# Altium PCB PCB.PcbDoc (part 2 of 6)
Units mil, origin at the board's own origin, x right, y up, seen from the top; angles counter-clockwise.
Board outline 7100 x 7000 mil, 4 copper layers (Top Layer, GND, VCC, Bottom Layer), stack 61.2 mil thick; 759 components, 507 nets, 2200 pads, 452 vias.
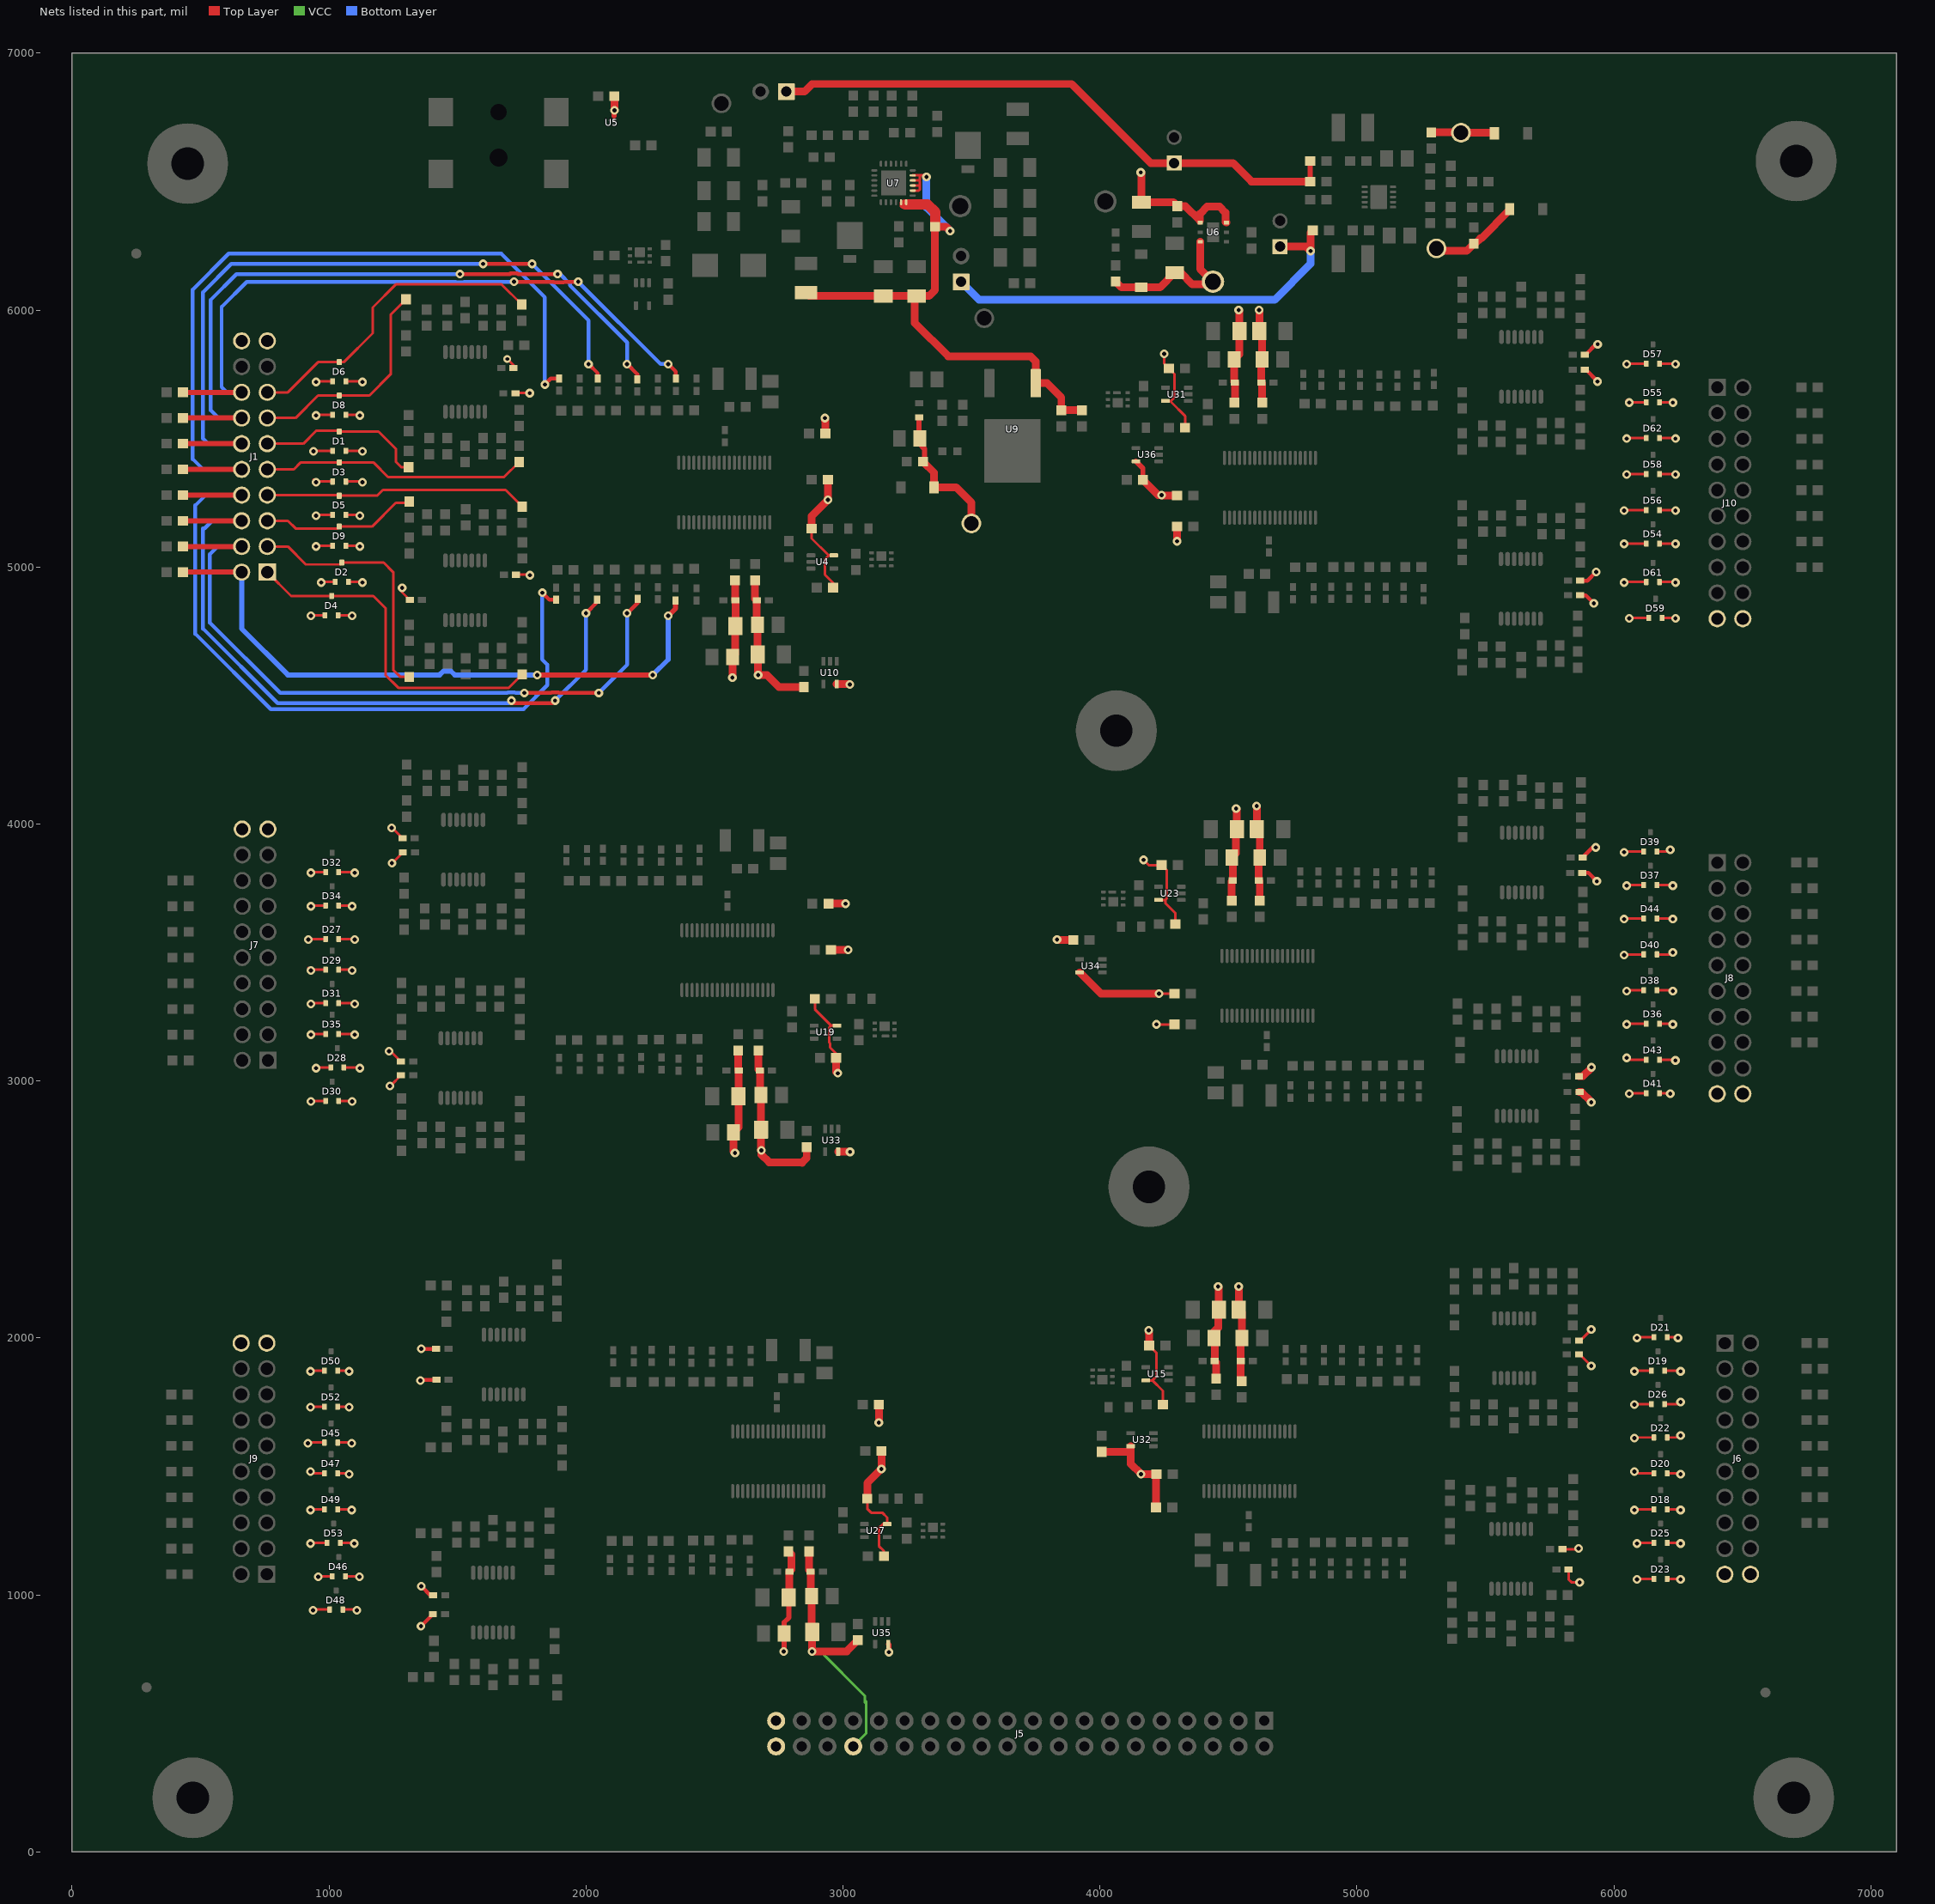
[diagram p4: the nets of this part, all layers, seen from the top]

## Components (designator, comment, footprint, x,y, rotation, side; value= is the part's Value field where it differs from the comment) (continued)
U24 "OPA4197IPWR" PW0014A_N 1679.76,1896.43 r270 top
U25 "OPA4197IPWR" PW0014A_N 1638.26,969.95 r270 top
U26 "ADS8688IDBT" DBT0038A_N 2748.26,1519.95 r270 top
U27 "SN74LVC1G17DCKR" DCK0005A_N 3128.25,1250 r0 top
U28 "OPA4197IPWR" PW0014A_N 5637.69,4914.98 r90 top
U29 "OPA4197IPWR" PW0014A_N 5639.69,5778.98 r90 top
U30 "ADS8688IDBT" DBT0038A_N 4661.89,5308.58 r90 top
U31 "SN74LVC1G17DCKR" DCK0005A_N 4300,5672.44 r180 top
U32 "SN74LVC1G17DCKR" DCK0005A_N 4164,1604 r180 top
U33 "SN74LVC1G17DCKR" DCK0005A_N 2956,2769 r270 top
U34 "SN74LVC1G17DCKR" DCK0005A_N 3966,3448 r180 top
U35 "SN74LVC1G17DCKR" DCK0005A_N 3151,853 r270 top
U36 "SN74LVC1G17DCKR" DCK0005A_N 4185,5437 r180 top
ZZ1 "This Assembly Note is for PCB labels only" AssemblyNoteLabel 11900,340 r90 top

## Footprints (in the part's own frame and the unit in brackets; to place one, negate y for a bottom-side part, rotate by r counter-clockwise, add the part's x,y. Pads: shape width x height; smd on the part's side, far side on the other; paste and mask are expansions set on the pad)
0402 [mm] "0402 from SM-752 data"
  rect 0.8x0.6 smd: 1(-0.6,0) 2(0.6,0)
  silkscreen extent -1.22,-0.52 1.22,0.52, body extent -0.55,-0.3 0.55,0.3, height 0.6
0603 [mm] "0603 from SM-752 data"
  rect 1x0.95 smd: 1(-0.8,0) 2(0.8,0)
  silkscreen extent -1.52,-0.69 1.52,0.69, body extent -0.87,-0.47 0.87,0.47, height 1
0805_HV [mil] "0805 with 30mil clearance between pads"
  rect 50x63 smd: 1(-40,0) 2(40,0)
  silkscreen extent -74,-40 74,40, body extent -43,-29 43,29, height 57
1206 [mm] "1206 from SM-752 data"
  rect 1.3x1.85 smd: 1(-1.45,0) 2(1.45,0)
  silkscreen extent -2.4,-1.21 2.4,1.21, body extent -1.7,-0.9 1.7,0.9, height 1.35
1210 [mm] "1210 from SM-752 data"
  rect 1.3x2.7 smd: 1(-1.45,0) 2(1.45,0)
  silkscreen extent -2.32,-1.57 2.32,1.57, body extent -1.7,-1.35 1.7,1.35, height 1.35
1210_280 [mm] "SMD, 2-Leads, Body 3.6x2.8mm, Height 2.8mm"
  rect 1.1x2.2 smd: 1(-1.65,0) 2(1.65,0)
  silkscreen extent -0.84,-1.4 0.84,1.4, body extent -1.8,-1.4 1.8,1.4, height 2.8
3216-18 [mm] "Based on AVX recommendation in http://www.avx.com/download/software/literature/AVX-Footprint-Library.pdf"
  rrect7% 1.4x1.8 smd: 1(-1.3,0) 2(1.3,0)
  silkscreen extent -1.9,-1.12 0.8,1.12, body extent -1.7,-0.9 1.7,0.9, height 1.82
6032-28 [mm] "Medium Density IPC based on Vishay Sprague 293D datasheet."
  rect 2.55x2.3 smd: 1(-2.375,0) 2(2.375,0)
  silkscreen extent -3.96,-1.75 3.2,1.82, body extent -3.15,-1.75 3.15,1.75, height 2.8
AssemblyNoteLabel [mil] "Assembly Note for PCB Labels"
CONN_PEC02SAAN [mm] "SULLINS"
  rrect7% 1.5x1.5 hole 1.016: 1(-1.27,0)
  round 1.5 hole 1.016: 2(1.27,0)
  silkscreen extent -2.54,-1.52 2.54,1.27, body extent -2.54,-1.27 2.54,1.27, height 8.38
CONN_ZSS-120-01-L-D-529 [mil] "Header 20x2 , 100 mil Pitch"
  rect 70x70 hole 40: 1(-950,-50)
  round 70 hole 40: 2(-950,50) 3(-850,-50) 4(-850,50) 5(-750,-50) 6(-750,50) 7(-650,-50) 8(-650,50) 9(-550,-50) 10(-550,50) 11(-450,-50) 12(-450,50) 13(-350,-50) 14(-350,50) 15(-250,-50) 16(-250,50) 17(-150,-50) 18(-150,50) 19(-50,-50) 20(-50,50) 21(50,-50) 22(50,50) 23(150,-50) 24(150,50) 25(250,-50) 26(250,50) 27(350,-50) 28(350,50) 29(450,-50) 30(450,50) 31(550,-50) 32(550,50) 33(650,-50) 34(650,50) 35(750,-50) 36(750,50) 37(850,-50) 38(850,50) 39(950,-50) 40(950,50)
  silkscreen extent -1075,-190 1075,183, body extent -1075,-190 1075,183, height 528
CUI_PJ-002AH-SMT [mm] "CUI"
  rect 2.8x2.4 smd: 1(-3.05,5.7) 1A(3.05,5.7) 2(-3.05,-5.7) 3(3.05,-5.7)
  round 1 hole 1.6 unplated: MH1(-3.05,0)
  round 1.524 hole 1.8 unplated: MH2(1.45,0)
  silkscreen extent -8.05,-4.5 6.75,5.45, body extent -8.05,-6.3 6.75,6.3, height 11.2
DBT0038A_N [mm] "TSSOP, 38-Leads, Body 9.7x4.4mm, Pitch 0.5mm, IPC Medium Density"
  oval 1.4x0.3 smd: 1(-2.95,4.5) 2(-2.95,4) 3(-2.95,3.5) 4(-2.95,3) 5(-2.95,2.5) 6(-2.95,2) 7(-2.95,1.5) 8(-2.95,1) 9(-2.95,0.5) 10(-2.95,0) 11(-2.95,-0.5) 12(-2.95,-1) 13(-2.95,-1.5) 14(-2.95,-2) 15(-2.95,-2.5) 16(-2.95,-3) 17(-2.95,-3.5) 18(-2.95,-4) 19(-2.95,-4.5) 20(2.95,-4.5) 21(2.95,-4) 22(2.95,-3.5) 23(2.95,-3) 24(2.95,-2.5) 25(2.95,-2) 26(2.95,-1.5) 27(2.95,-1) 28(2.95,-0.5) 29(2.95,0) 30(2.95,0.5) 31(2.95,1) 32(2.95,1.5) 33(2.95,2) 34(2.95,2.5) 35(2.95,3) 36(2.95,3.5) 37(2.95,4) 38(2.95,4.5)
  silkscreen extent -3.5,-4.9 1.5,4.9, body extent -3.21,-4.85 3.21,4.85, height 1.2
DCK0005A_N [mm] "SOT353, 5-Leads, Body 2x1.3mm, Pitch 0.65mm, Lead Span 2.1mm, IPC Medium Density"
  rrect25% 0.85x0.4 smd: 1(-1.125,0.65) 2(-1.125,0) 3(-1.125,-0.65) 4(1.125,-0.65) 5(1.125,0.65)
  silkscreen extent -1.48,-1.02 0.55,1.1, body extent -1.14,-1 1.14,1, height 0.95
DQK0006C [mm] "WSON"
  rrect12% 0.9x0.86 on Top Paste: 0(0,0.325)
  rrect34% 0.7x0.29 on Top Paste: 0(0.095,-0.65)
  rrect33% 0.45x0.3 smd: 1(-0.975,0.65) 2(-0.975,0) 3(-0.975,-0.65) 4(0.975,-0.65) 5(0.975,0) 6(0.975,0.65)
  rrect33% 0.75x0.3 smd paste-0.15: 7(0.095,-0.65)
  rrect11% 1x0.95 smd paste-0.5: 8(0,0.325)
  silkscreen extent -1.15,-1.15 1.15,1.15, body extent -1,-1 1,1, height 0.82
DSC0010J [mm] "SON, 10-Leads, Body 3x3mm, Pitch 0.5mm, Thermal Pad 2.4x1.65mm, TI Recommended"
  rrect40% 0.6x0.25 smd: 1(-1.4,1) 2(-1.4,0.5) 3(-1.4,0) 4(-1.4,-0.5) 5(-1.4,-1) 6(1.4,-1) 7(1.4,-0.5) 8(1.4,0) 9(1.4,0.5) 10(1.4,1)
  rrect40% 0.25x0.34 on Top Paste: 11(-0.25,-1.53) 11(-0.25,1.53) 11(0.25,-1.53) 11(0.25,1.53)
  rrect9% 1.5x1.06 on Top Paste: 11(0,-0.63) 11(0,0.63)
  rrect12% 1.65x2.4 smd paste-1 mask-2: 11(0,0)
  Top Layer region: -0.775,-1.25 -0.425,-1.25 -0.425,-1.65 -0.417,-1.688 -0.396,-1.721 -0.363,-1.742 -0.325,-1.75 -0.325,-1.75 -0.325,-1.75 -0.175,-1.75 -0.175,-1.75 -0.137,-1.742 -0.104,-1.721 -0.083,-1.688 -0.075,-1.65 -0.075,-1.65 -0.075,-1.25 0.075,-1.25 0.075,-1.65 0.083,-1.688 0.104,-1.721 0.137,-1.742 0.175,-1.75 0.175,-1.75 0.175,-1.75 0.325,-1.75 0.325,-1.75 0.363,-1.742 0.396,-1.721 0.417,-1.688 0.425,-1.65 0.425,-1.65 0.425,-1.25 0.775,-1.25 0.813,-1.242 0.846,-1.221 0.867,-1.188 0.875,-1.15 0.875,-1.15 0.875,1.15 0.867,1.188 0.846,1.221 0.813,1.242 0.775,1.25 0.775,1.25 0.425,1.25 0.425,1.65 0.417,1.688 0.396,1.721 0.363,1.742 0.325,1.75 0.325,1.75 0.175,1.75 0.137,1.742 0.104,1.721 0.083,1.688 0.075,1.65 0.075,1.65 0.075,1.25 -0.075,1.25 -0.075,1.65 -0.083,1.688 -0.104,1.721 -0.137,1.742 -0.175,1.75 -0.175,1.75 -0.325,1.75 -0.363,1.742 -0.396,1.721 -0.417,1.688 -0.425,1.65 -0.425,1.65 -0.425,1.25 -0.775,1.25 -0.813,1.242 -0.846,1.221 -0.867,1.188 -0.875,1.15 -0.875,1.15 -0.875,-1.15 -0.867,-1.188 -0.846,-1.221 -0.813,-1.242 -0.775,-1.25
  silkscreen extent -1.63,-1.63 1.63,1.63, body extent -1.5,-1.5 1.5,1.5, height 0.81
FCC_disclaimer [mil]
Fiducial10-20 [mm]
  round 1 smd mask+0.5: 1(0,0)
  Top Layer keep-out circle w1.178: c0,0 r0.5
Keystone5010 [mil] "Keystone Multipurpose loops"
  round 87 hole 63: 1(0,0)
  silkscreen extent -70,-70 70,70, body extent -63,-63 63,62, height 319
Keystone5126 [mil] "Keystone Multipurpose loops"
  round 87 hole 63: 1(0,0)
  silkscreen extent -70,-70 70,70, body extent -63,-63 63,62, height 319
Keystone_1902C#1 [mil] "Hex Standoff, 4-40 threaded, nylon"
  body extent -145,-126 146,126, height 501
Keystone_1902C#2 [mil] "Hex Standoff, 4-40 threaded, nylon"
  round 1 on Mech4: 0(0,0)
  body extent -145,-126 146,126, height 501
KVU0003A_N [mm] "DPAK, 3-Leads, Body 6.6x6.1mm, Pitch 2.29mm, IPC Medium Density"
  rrect10% 2.8x1 smd: 1(-4.2,2.29) 3(-4.2,-2.29)
  rrect10% 0.98x1.13 on Top Paste: 4(0.14,1.995) 4(0.14,0.665) 4(0.14,-0.665) 4(0.14,-1.995) 4(1.32,1.995) 4(1.32,0.665) 4(1.32,-0.665) 4(1.32,-1.995) 5(2.5,1.995) 5(2.5,-0.665) 5(2.5,0.665) 5(2.5,-1.995) 6(3.68,1.995) 6(3.68,-0.665) 6(3.68,0.665) 6(3.68,-1.995) 7(4.86,1.995) 7(4.86,-0.665) 7(4.86,0.665) 7(4.86,-1.995)
  rrect2% 6.3x5.55 smd paste-3: 4(2.5,0)
  silkscreen extent -4.35,-3.35 -1.05,3.47, body extent -5.05,-3.26 5.05,3.26, height 2.41
Label_650x200 [mil] "Thermal Transfer Label"
  silkscreen extent -325,-100 325,100, body extent -325,-100 325,100, height 1
LDE06A [mm] "PSON, 6-Leads, Body 2.92x3.29 mm, Pitch 0.95mm, NSC Recommended"
  rect 0.5x0.35 smd paste-0.175 mask+0.051: 1(-1.295,0.95) 2(-1.295,0) 3(-1.295,-0.95) 4(1.295,-0.95) 5(1.295,0) 6(1.295,0.95)
  rect 1.2x1.92 smd paste-0.6 mask+0.051: 7(0,0)
  silkscreen extent -2.52,-1.66 1.85,1.67, body extent -1.69,-1.51 1.69,1.51, height 0.8
"LG L29K_GREEN" [mm] "OSRAM"
  rect 0.8x0.8 smd paste-0.4: 1(-0.75,0) 2(0.75,0)
  silkscreen extent -0.1,-0.5 1.45,0.5, body extent -0.9,-0.45 0.9,0.45, height 0.67
LG_M67K_Green [mm] "SMD, 2-Leads, Body 2x1.4mm, Pitch 2mm"
  rect 0.8x1 smd mask+0: 1(-1,0) 2(1,0)
  silkscreen extent -2.1,-1 1.05,1, body extent -1.05,-0.75 1.05,0.75, height 1.4
Mill-Max_0253-0-15-15-30-27-10-0 [mm] "Pin Receptacle, Dia 0.015-0.025\", Length 0.173\", TH"
  round 1.95 hole 1.448: 1(0,0)
  silkscreen extent -1.4,-1.4 1.4,1.4, body extent -0.91,-0.91 0.91,0.91, height 0.79
MMZ1608_095 [mm] "TDK"
  rect 0.6x0.8 smd: 1(-0.7,0) 2(0.7,0)
  silkscreen extent -0.15,-0.58 0.15,0.58, body extent -0.87,-0.47 0.87,0.47, height 0.95
"NY PMS 440 0025 PH" [mm] "4-40 nylon screw and mounting hole"
  round 8 hole 3.2: 1(0,0)
  body extent -3.3,-3.3 3.3,3.3, height 2.69
Pb-Free_Overlay_Small [mil]
  silkscreen extent -46,-46 46,46
POWERMITE [mil] "On Semi recommended land pattern, 457-04.pdf Rev 04E dated 2008-11-26"
  rect 105x100 smd: 1(-46,0)
  rect 30x50 smd: 2(46,0)
  silkscreen extent -124,-63 61,63, body extent -94,-40 59,40, height 45
PW0014A_N [mm] "TSOP, 14-Leads, Body 5x4.4mm, Pitch 0.65mm, IPC Medium Density"
  oval 1.4x0.45 smd: 1(-2.95,1.95) 2(-2.95,1.3) 3(-2.95,0.65) 4(-2.95,0) 5(-2.95,-0.65) 6(-2.95,-1.3) 7(-2.95,-1.95) 8(2.95,-1.95) 9(2.95,-1.3) 10(2.95,-0.65) 11(2.95,0) 12(2.95,0.65) 13(2.95,1.3) 14(2.95,1.95)
  silkscreen extent -3.4,-2.55 1.85,2.55, body extent -3.21,-2.5 3.21,2.5, height 1
RGE0024B [mm] "QFN, 24-Leads, Body 4x4mm, Pitch 0.5mm, Thermal Pad 2.45x2.45mm, TI Recommended"
  oval 0.6x0.24 smd: 1(-1.9,1.25) 2(-1.9,0.75) 3(-1.9,0.25) 4(-1.9,-0.25) 5(-1.9,-0.75) 6(-1.9,-1.25) 13(1.9,-1.25) 14(1.9,-0.75) 15(1.9,-0.25) 16(1.9,0.25) 17(1.9,0.75) 18(1.9,1.25)
  oval 0.24x0.6 smd: 7(-1.25,-1.9) 8(-0.75,-1.9) 9(-0.25,-1.9) 10(0.25,-1.9) 11(0.75,-1.9) 12(1.25,-1.9) 19(1.25,1.9) 20(0.75,1.9) 21(0.25,1.9) 22(-0.25,1.9) 23(-0.75,1.9) 24(-1.25,1.9)
  rect 2.45x2.45 smd paste-1.225: 25(0,0)
  silkscreen extent -2.22,-2.22 2.22,2.22, body extent -2.07,-2.07 2.07,2.07, height 1.01
SOD-123 [mm] "On Semi recommended land pattern"
  rect 0.915x1.22 smd: 1(-1.637,0) 2(1.637,0)
  silkscreen extent -2.74,-1.17 2.03,1.17, body extent -1.93,-0.9 1.93,0.9, height 1.35
SOT-323 [mm] "Diodes Inc recommended land pattern.  2016-02-24"
  rrect21% 0.6x0.47 smd: 1(-0.95,0.65) 2(-0.95,-0.65) 3(0.95,0)
  silkscreen extent -1.14,-1.22 0.77,1.22, body extent -1.13,-1.13 1.12,1.12, height 1.13
Sullins_SBH11-xxxC-D10-ST [mm] "Header (Shrouded), 2.54mm, 10x2, TH"
  rect 1.7x1.7 hole 1.2: 1(-1.27,11.43)
  round 1.7 hole 1.2: 2(1.27,11.43) 3(-1.27,8.89) 4(1.27,8.89) 5(-1.27,6.35) 6(1.27,6.35) 7(-1.27,3.81) 8(1.27,3.81) 9(-1.27,1.27) 10(1.27,1.27) 11(-1.27,-1.27) 12(1.27,-1.27) 13(-1.27,-3.81) 14(1.27,-3.81) 15(-1.27,-6.35) 16(1.27,-6.35) 17(-1.27,-8.89) 18(1.27,-8.89) 19(-1.27,-11.43) 20(1.27,-11.43)
  silkscreen extent -5.25,-16.45 4.4,16.45, body extent -4.4,-16.45 4.7,16.45, height 9.11
TI_Stacked_Overlay_Small [mil]
  silkscreen extent -418,-98 418,98
TSW-102-07-G-S [mm] "Samtec 100mil, 1x2, 230 mil above insulator"
  rrect6% 1.65x1.65 hole 1.016: 1(-1.27,0)
  round 1.65 hole 1.016: 2(1.27,0)
  silkscreen extent -2.54,-1.27 2.54,1.65, body extent -2.54,-1.27 2.54,1.27, height 8.38
VLF504012MT [mm] "TDK"
  rect 1.3x2.2 smd: 1(-1.45,0) 2(1.45,0)
  silkscreen extent -2.2,-2.7 2.2,2.7, body extent -2.15,-2.65 2.15,2.65, height 1.2
YFP0004ABAB [mm] "TI DSBGA 0.806x0.806mm"
  round 0.23 smd paste-0.13 mask+0.038: A1(-0.2,0.2) A2(0.2,0.2) B1(-0.2,-0.2) B2(0.2,-0.2)
  silkscreen extent -0.5,-0.5 0.5,0.5, body extent -0.43,-0.43 0.43,0.43, height 0.5

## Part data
C1 C2 C11 C12 C76 C77 C86 C87 C114 C115 C124 C125 C152 C153 C162 C163 C190 C191 C200 C201 C228 C229 C238 C239: "CAP, CERM, 0.1 µF, 50 V,+/- 10%, X7R, 0603"
C3 C4 C17 C18 C30 C31 C35 C36 C78 C79 C92 C93 C105 C106 C110 C111 C116 C117 C130 C131 C143 C144 C148 C149 C154 C155 C168 C169 C181 C182 C186 C187 C192 C193 C206 C207 C219 C220 C224 C225 C230 C231 C244 C245 C257 C258 C262 C263: "CAP, CERM, 47 pF, 50 V,+/- 5%, C0G/NP0, 0603"
C5 C8 C80 C83 C118 C121 C156 C159 C194 C197 C232 C235: "CAP, CERM, 1 µF, 10 V, +/- 10%, X7R, 0805"
C6 C9 C81 C84 C119 C122 C157 C160 C195 C198 C233 C236: "CAP, TA, 10 µF, 10 V, +/- 20%, 3 ohm, SMD"
C7 C10 C82 C85 C120 C123 C158 C161 C196 C199 C234 C237: "CAP, CERM, 0.1 µF, 10 V, +/- 10%, X5R, 0402"
C13 C14 C22 C23 C32 C33 C37 C38 C88 C89 C97 C98 C107 C108 C112 C113 C126 C127 C135 C136 C145 C146 C150 C151 C164 C165 C173 C174 C183 C184 C188 C189 C202 C203 C211 C212 C221 C222 C226 C227 C240 C241 C248 C250 C259 C260 C264 C265: "CAP, CERM, 100 pF, 50 V,+/- 1%, C0G/NP0, 0603"
C15 C16 C19 C20 C21 C27 C28 C29 C48 C90 C91 C94 C95 C96 C102 C103 C104 C128 C129 C132 C133 C134 C140 C141 C142 C166 C167 C170 C171 C172 C178 C179 C180 C204 C205 C208 C209 C210 C216 C217 C218 C242 C243 C246 C247 C249 C254 C255 C256: "CAP, CERM, 0.01 µF, 50 V,+/- 10%, X7R, 0603"
C24 C99 C137 C175 C213 C251: "CAP, CERM, 10 µF, 10 V,+/- 10%, X7R, 0805"
C25 C100 C138 C176 C214 C252: "CAP, CERM, 22 µF, 16 V,+/- 10%, X7R, 1210"
C26 C101 C139 C177 C215 C253 C272: "CAP, CERM, 1 µF, 16 V,+/- 10%, X7R, 0603"
C34 C75 C109 C147 C185 C223 C261 C266 C267 C268 C269 C270 C271 C273: "CAP, CERM, 0.1 µF, 16 V, +/- 10%, X7R, 0603"
C39: library part GRM31CR71E106KA12L, "CAP, CERM, 10uF, 25V, +/-10%, X7R, 1206"
C40: "CAP, CERM, 0.1uF, 25V, +/-5%, X7R, 0603"
C41 C43 C44 C45 C47 C54 C56 C57 C58 C59: library part C3216X7R1E475M, "CAP, CERM, 4.7 µF, 25 V, +/- 20%, X7R, 1206"
C42: "CAP, TA, 4.7 µF, 25 V, +/- 10%, 2 ohm, SMD"
C46 C51 C60 C67: "CAP, CERM, 0.01 µF, 6.3 V, +/- 10%, X7R, 0603"
C49: library part C0603C224K4RACTU, "CAP, CERM, 0.22 µF, 6.3 V, +/- 10%, X7R, 0603"
C50 C52: "CAP, CERM, 10 pF, 50 V, +/- 5%, C0G/NP0, 0603"
C53 C61 C65: "CAP, CERM, 0.1 µF, 25 V,+/- 5%, X7R, 0603"
C55 C63 C69: "CAP, CERM, 1 µF, 25 V, +/- 10%, X5R, 0603"
C62 C68: library part GMK325AB7106MM-T, "CAP, CERM, 10uF, 35V, +/-20%, X7R, 1210"
C64 C66: "CAP, CERM, 2.2uF, 10V, +/-10%, X7R, 0805"
C70: library part C2012X5R1H475K125AB, "CAP, CERM, 4.7uF, 50V, +/-10%, X5R, 0805"
C71 C74: "CAP, CERM, 0.1uF, 50V, +/-10%, X7R, 0603"
C72 C73: library part GRM188R61H105KAALD, "CAP, CERM, 1uF, 50V, +/-10%, X5R, 0603"
D1 D2 D3 D4 D5 D6 D8 D9 D18 D19 D20 D21 D22 D23 D25 D26 D27 D28 D29 D30 D31 D32 D34 D35 D36 D37 D38 D39 D40 D41 D43 D44 D45 D46 D47 D48 D49 D50 D52 D53 D54 D55 D56 D57 D58 D59 D61 D62: "Diode, TVS, Uni, 70 V, SOT-323"
D7 D13 D17 D24 D33 D42 D51 D60: "LED, Green, SMD"
D10 D15: "Diode, Schottky, 20 V, 1 A, POWERMITE"
D11 D14: "Diode, Zener, 15V, 1W, SOD-123"
D12: "Diode, Zener, 5.6 V, 500 mW, SOD-123"
D16: library part MMSZ4685-V, "Diode, Zener, 3.6V, 500mW, SOD-123"
FB1: "Ferrite Bead, 1000 ohm @ 100 MHz, 0.3 A, 0603"
FID1 FID2 FID3: "Fiducial mark.  There is nothing to buy or mount."
H1 H2 H3 H4 H9 H10: "Machine Screw, Round, #4-40 x 1/4, Nylon, Philips panhead"
H5 H6 H7 H8 H11 H12: "Standoff, Hex, 0.5\"L #4-40 Nylon"
J1 J6 J7 J8 J9 J10: "Header (Shrouded), 2.54mm, 10x2, Gold, Black, TH"
J2 J4: library part TSW-102-07-G-S, "Header, 100mil, 2x1, Gold, TH"
J3: "Power Jack, SMT"
J5: "Elevated Header, 100 mil, 20x2, TH"
J11 J12: "Header, 100mil, 2x1, Tin, TH"
L1 L2: "Inductor, Shielded, Ferrite, 4.7 µH, 1.83 A, 0.1 ohm, SMD"
LBL1: library part THT-14-423-10, "Thermal Transfer Printable Labels, 0.650\" W x 0.200\" H - 10,000 per roll"
Logo1: library part TI_Logo, "Texas Instrument Corporate Signature"
Logo2: library part Pb-Free
Logo3: library part FCC_disclaimer, "FCC_disclaimer"
Q1 Q2 Q3 Q4 Q5 Q6 Q7: "MOSFET, N-CH, 30 V, 22 A, DQK0006C (WSON-6)"
R1 R2 R3 R4 R18 R19 R20 R21 R35 R36 R37 R38 R40 R41 R44 R45 R73 R74 R75 R76 R90 R91 R92 R93 R107 R108 R109 R110 R112 R113 R116 R117 R118 R119 R120 R121 R135 R136 R137 R138 R152 R153 R154 R155 R157 R158 R161 R162 R163 R164 R165 R166 R180 R181 R182 R183 R197 R198 R199 R200 R202 R203 R206 R207 R208 R209 R210 R211 R225 R226 R227 R228 R242 R243 R244 R245 R247 R248 R251 R252 R253 R254 R255 R256 R270 R271 R272 R273 R287 R288 R289 R290 R292 R293 R296 R297: "RES, 51 k, 5%, 0.1 W, 0603"
R5 R6 R7 R8 R9 R10 R11 R12 R47 R51 R53 R58 R59 R61 R65 R67 R77 R78 R79 R80 R81 R82 R83 R84 R122 R123 R124 R125 R126 R127 R128 R129 R167 R168 R169 R170 R171 R172 R173 R174 R212 R213 R214 R215 R216 R217 R218 R219 R257 R258 R259 R260 R261 R262 R263 R264 R298 R299 R300 R301 R302 R303 R304 R305 R306 R307 R308 R309: "RES, 0, 5%, 0.1 W, 0603"
R13 R14 R15 R17 R22 R24 R25 R26 R27 R28 R29 R30 R31 R32 R33 R34 R85 R86 R87 R89 R94 R96 R97 R98 R99 R100 R101 R102 R103 R104 R105 R106 R130 R131 R132 R134 R139 R141 R142 R143 R144 R145 R146 R147 R148 R149 R150 R151 R175 R176 R177 R179 R184 R186 R187 R188 R189 R190 R191 R192 R193 R194 R195 R196 R220 R221 R222 R224 R229 R231 R232 R233 R234 R235 R236 R237 R238 R239 R240 R241 R265 R266 R267 R269 R274 R276 R277 R278 R279 R280 R281 R282 R283 R284 R285 R286: "RES, 357, 1%, 0.063 W, 0402"
R16 R23 R88 R95 R133 R140 R178 R185 R223 R230 R268 R275: "RES, 47.0 k, 1%, 0.1 W, 0603"
R39 R43 R68 R72 R111 R115 R156 R160 R201 R205 R246 R250 R291 R295: "RES, 300, 5%, 0.1 W, 0603"
R42 R71 R114 R159 R204 R249 R294: "RES, 0, 1%, 0.1 W, AEC-Q200 Grade 0, 0603"
R46: "RES, 0 ohm, 5%, 0.25W, 1206"
R48: "RES, 820, 1%, 0.1 W, 0603"
R49: "RES, 576 k, 1%, 0.1 W, 0603"
R50 R54 R55: "RES, 49.9 k, 0.1%, 0.1 W, 0603"
R52: library part RC0603FR-07620KL, "RES SMD 620K OHM 1% 1/10W 0603"
R56: library part RT0603DRE071RL, "RES SMD 1 OHM 5% 1/10W 0603"
R57: "RES, 1.0 k, 5%, 0.1 W, 0603"
R60 R62: "RES, 274 k, 1%, 0.1 W, 0603"
R63: "RES, 31.6 k, 1%, 0.1 W, 0603"
R64: "RES, 300 ohm, 5%, 0.1W, 0603"
R66: "RES, 27.4 k, 1%, 0.1 W, 0603"
R69 R310 R311 R312 R313 R314 R315 R316 R317 R318 R319 R320 R321 R322 R323 R324 R325 R326 R327 R328 R329 R330 R331 R332 R333 R334 R335 R336 R337 R338: "RES, 0, 5%, 0.063 W, 0402"
R70: library part CRCW0805330KJNEA, "RES, 0 ohm, 5%, 0.125W, 0805"
TP1 TP5: library part 5010, "Test Point, Multipurpose, Red, TH"
TP2 TP4 TP6 TP7 TP8: library part 0253-0-15-15-30-27-10-0, "Pin Receptacle, Dia 0.015-0.025\", Length 0.173\", Gold, TH"
TP3: library part 5126, "Test Point, Multipurpose, Green, TH"
U1 U2 U12 U13 U16 U17 U20 U21 U24 U25 U28 U29: "36-V, Precision, Rail-to-Rail Input Output, Low Offset Voltage Op Amp, PW0014A (TSSOP-14)"
U3 U14 U18 U22 U26 U30: "16-Bit, 500-kSPS, 8-Channel, Single-Supply, SAR ADCs with Bipolar Input Ranges, DBT0038A (TSSOP-38)"
U4 U10 U11 U15 U19 U23 U27 U31 U32 U33 U34 U35 U36: "SINGLE SCHMITT-TRIGGER BUFFER, DCK0005A (SOT-SC70-5)"
U5: "Single Channel Ultra-Low Resistnace Load Switch, YFP0004ABAB (DSBGA-4)"
U6: "Micropower 250 mA Low-Noise Ultra Low-Dropout Regulator, 6-pin LLP, Pb-Free"
U7: "Postive and Negative Output DC-DC Converter, 2.7 to 5.5 V, -40 to 85 degC, 24-pin QFN (RGE24), Green (RoHS & no Sb/Br)"
U8: "Wide-VIN (±33 V), 150-mA, Spilt-Rail Output, Positive and Negative LDO Voltage Regulator with Startup Tracking, DSC0010J"
U9: "Automotive 300-mA 40-V Low-Dropout Regulator With Ultra-Low Quiescent Current, KVU0003A (TO-252-3)"
ZZ1: library part AssemblyNoteLabel

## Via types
v1: diameter 34, hole 16, Top Layer to Bottom Layer, 440 vias
v2: diameter 19.68, hole 7.87, Top Layer to Bottom Layer, 11 vias
v3: diameter 30, hole 14, Top Layer to Bottom Layer, 1 vias

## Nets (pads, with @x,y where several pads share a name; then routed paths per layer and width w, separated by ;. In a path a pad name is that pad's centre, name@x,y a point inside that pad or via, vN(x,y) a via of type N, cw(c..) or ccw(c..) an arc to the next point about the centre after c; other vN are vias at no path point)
+3.3V: C8.1 C9.1 C10.1 C34.1 C70.1 C71.1 C83.1 C84.1 C85.1 C109.1 C121.1 C122.1 C123.1 C147.1 C159.1 C160.1 C161.1 C185.1 C197.1 C198.1 C199.1 C223.1 C235.1 C236.1 C237.1 C261.1 C266.1 C267.1 C268.1 C269.1 C270.1 C271.1 D16.1 FB1.2 J5.34 R16.2 R23.2 R39.2 R88.2 R95.2 R111.2 R133.2 R140.2 R156.2 R178.2 R185.2 R201.2 R223.2 R230.2 R246.2 R268.2 R275.2 R291.2 R299.2 R301.2 R303.2 R305.2 R307.2 R309.2 TP6.1 U4.5 U10.5 U15.5 U19.5 U23.5 U27.5 U31.5 U32.5 U33.5 U34.5 U35.5 U36.5 | length 8080.9
  Top Layer w10: v1@2681.18,2731.18 v1(2682.36,2730) ; R39.2@2878.5,5150 2878.5,5111.5 2944.41,5045.59 2945.59,5045.59 ; v1(2880,780) v1@2880.15,780.15 ; R156.2@2890.87,3320 2890.87,3279.13 2954.41,3215.59 ; C34.1@2961.5,4920 2961.5,4938.5 2930,4970 2930,5030 2945.59,5045.59 ; U4.5@2964.29,5045.59 2945.59,5045.59 ; C147.1@2973.86,3090 2973.86,3106.14 2950,3130 2950,3146.45 2947.05,3149.4 2947.05,3208.23 2954.41,3215.59 ; U19.5@2976.65,3215.59 2954.41,3215.59 ; R246.2@3094.86,1374.17 3094.86,1335.14 3110,1320 3153.15,1320 3172.54,1300.61 U27.5@3172.54,1275.59 3155.59,1275.59 3140,1260 3140,1190 3159.75,1170.25 C223.1@3159.75,1150 ; R223.2@3139.75,1739.95 R223.2@3140,1739.7 ; v1(4170,3860) 4190,3840 C185.1@4240.55,3840 4260,3820.55 4260,3710 4254.41,3704.41 ; U15.5@4179.06,1834.41 4204.41,1834.41 ; C109.1@4191.85,1970 4220,1941.85 4220,1850 4204.41,1834.41 ; v1(4220,3220) R185.2@4290.55,3220 ; U23.5@4227.75,3704.41 4254.41,3704.41 ; v1(4230,3340) R178.2@4290.55,3340 ; R111.2@4244.84,1740 4244.84,1793.98 4204.41,1834.41 ; v1(4250,5830) 4250,5790.94 C261.1@4268.5,5772.44 4290,5750.94 4290,5660 4276.85,5646.85 4276.85,5642.44 4331.5,5587.8 R291.2@4331.5,5542.44 ; R201.2@4293.54,3610 4293.54,3653.15 4254.41,3692.28 4254.41,3704.41
  Top Layer w20: C199.1@2868.26,1096.33 C199.1@2874.63,1089.95 ; C197.1@2874.63,999.01 C197.1@2878.26,995.38 ; C198.1@2878.26,857.27 C198.1@2880.15,855.38 ; U35.5@3176.59,808.71 3179,806.3 v1(3179,777) ; FB1.2@3296.18,5582.83 3296.18,5503.82 C70.1@3300,5500 3300,5477 3317,5460 3317,5415.5 C71.1@3311.5,5410 ; U36.5@4140.71,5411.41 4167.5,5384.62 C271.1@4167.5,5339
  Top Layer w30: R299.2@2658.26,4948.5 2658.26,4876.38 C10.1@2664.63,4870 2664.63,4779.01 C8.1@2668.26,4775.38 2668.26,4660.56 C9.1@2668.82,4660 2668.82,4591.18 2670,4590 v1(2670,4580) 2704,4580 2751.5,4532.5 C266.1@2848,4532.5 ; R303.2@2670.62,3118.5 2670.62,3046.38 C123.1@2677,3040 2677,2949.01 C121.1@2680.62,2945.38 2680.62,2810.56 C122.1@2681.18,2810 v1@2681.18,2731.18 ; v1(2682.36,2730) 2682.36,2713.64 2713,2683 2840,2683 2841,2682 2859,2700 C268.1@2859,2742.5 ; C199.1@2868.26,1096.33 R307.2@2868.26,1168.45 ; C197.1@2874.63,999.01 C199.1@2874.63,1089.95 ; C198.1@2878.26,857.27 C197.1@2878.26,995.38 ; R39.2@2878.5,5150 2878.5,5198.5 v1(2941.5,5261.5) R23.2@2941.5,5339.95 ; v1(2880,780) 3014.5,780 C270.1@3058,823.5 ; v1@2880.15,780.15 C198.1@2880.15,855.38 ; v1(2930,5580) 2930,5570 2931.5,5568.5 R16.2@2931.5,5519.95 ; R133.2@2943.86,3689.95 2999.95,3689.95 3000,3690 v1(3010,3690) ; R140.2@2953.86,3509.95 v1(3020,3510) v1(3020,3510) ; C147.1@2973.86,3090 2973.86,3036.14 v1(2980,3030) ; U10.5@2975.59,4544.71 3025.29,4544.71 v1(3027,4543) ; U33.5@2981.59,2724.71 3027.29,2724.71 v1(3028,2724) ; R246.2@3094.86,1374.17 3094.86,1434.86 v1(3150,1490) 3150,1559.7 R230.2@3149.75,1559.95 ; v1(3140,1670) R223.2@3140,1739.7 ; C71.1@3311.5,5410 3354.47,5367.03 D16.1@3354.47,5310 3440,5310 3500,5250 TP6.1@3500,5170 ; v1(3833,3550) 3834,3549 C269.1@3896.5,3549 ; U34.5@3921.71,3422.41 4004.12,3340 v1(4230,3340) ; C267.1@4007,1556.5 4116.2,1556.5 4119.71,1553 ; U32.5@4119.71,1578.41 4119.71,1553 ; C271.1@4167.5,5339 4226.5,5280 v1(4240,5280) 4241.74,5278.26 R268.2@4300.4,5278.26 ; v1(4190,2030) 4190,2020 4191.85,2018.15 C109.1@4191.85,1970 ; R95.2@4218.5,1340 4218.5,1467.95 R88.2@4220.55,1470 v1(4160,1470) 4119.71,1510.29 4119.71,1553 ; v1(4300,5100) 4300.4,5100.4 R275.2@4300.4,5158.26 ; R301.2@4452.05,1841.5 4452.05,1904.92 C85.1@4446.97,1910 4446.97,1996.38 C83.1@4443.35,2000 4443.35,2023 4460.35,2040 4460.35,2107.12 C84.1@4463.23,2110 4463.23,2196.77 v1(4460,2200) ; R305.2@4513.35,3701.5 4513.35,3776.38 C161.1@4516.97,3780 4516.97,3866.38 C159.1@4513.35,3870 4530,3886.65 4530,3976.77 C160.1@4533.23,3980 4533.23,4056.77 v1(4530,4060) ; R309.2@4523.19,5639.76 4525.51,5642.08 C237.1@4525.51,5718.26 4523.19,5720.59 C235.1@4523.19,5808.26 4543.07,5828.15 C236.1@4543.07,5918.26 4543.07,5996.93 v1(4540,6000)
  VCC w10: v1(2880,780) 2912.49,780 3085.01,607.49 3085.01,580 3090,584.99 3090,460 J5.34@3040,410
+5V: C5.1 C6.1 C7.1 C41.1 C80.1 C81.1 C82.1 C118.1 C119.1 C120.1 C156.1 C157.1 C158.1 C194.1 C195.1 C196.1 C232.1 C233.1 C234.1 D12.1 R48.2 R298.2 R300.2 R302.2 R304.2 R306.2 R308.2 TP1.1 U6.6 | length 2931.9
  Top Layer w20: v1(2770,780) 2771.33,781.33 C194.1@2771.33,849.95 2771.33,893.02 2789.44,911.13 C195.1@2789.44,989.95 C195.1@2791.88,992.39 ; C196.1@2791.88,1089.95 C196.1@2800,1098.07
  Top Layer w30: v1(2570,4570) C5.1@2570,4650 2581.18,4661.18 C6.1@2581.18,4770 2581.88,4770.7 C7.1@2581.88,4870 2580,4871.88 R298.2@2580,4948.45 ; v1(2580,2720) 2573.69,2726.31 C118.1@2573.69,2799.95 2593.54,2819.81 C119.1@2593.54,2940 2594.24,2940.7 C120.1@2594.24,3040 2592.36,3041.88 R302.2@2592.36,3118.45 ; R306.2@2788.26,1168.45 2800,1156.71 C196.1@2800,1098.07 ; C195.1@2791.88,992.39 C196.1@2791.88,1089.95 ; R48.2@4061.32,6111.26 4084.29,6088.29 D12.1@4161.32,6088.29 4233.94,6088.29 C41.1@4291.32,6145.67 4314.33,6145.67 4360,6100 4429.19,6100 TP1.1@4440,6110.81 4390.33,6160.47 U6.6@4390.33,6265.35 ; v1(4540,2200) 4540.87,2199.13 C81.1@4540.87,2110 4552.05,2098.82 C80.1@4552.05,2000 4548.43,1996.38 C82.1@4548.43,1910 4548.43,1835.12 R300.2@4552.05,1831.5 ; v1(4610,4070) 4610.87,4069.13 C157.1@4610.87,3980 4622.05,3968.82 C156.1@4622.05,3870 4618.43,3866.38 C158.1@4618.43,3780 4622.05,3776.38 R304.2@4622.05,3701.5 ; v1(4620,6000) 4620.71,5999.29 C233.1@4620.71,5918.26 4631.89,5907.08 C232.1@4631.89,5808.26 4628.27,5804.64 C234.1@4628.27,5718.26 4631.89,5714.64 R308.2@4631.89,5639.76
+5V_IN: C39.1 C40.1 C47.1 C56.1 C73.1 C74.1 C273.1 L1.1 R56.1 U5.A1 U6.3 U6.4 U7.5 U7.6 U7.8 U7.9 U7.10 U7.11 U9.1 | length 3165.4
  Top Layer w6: U5.A1@2107.87,6738.19 2107.87,6766.87 v1@2109,6768
  Top Layer w10: U7.5@3226.46,6419.77 3226.46,6403.54 3230,6400 3240,6400 3246.14,6406.14 U7.6@3246.14,6419.77 ; U7.8@3271.73,6465.04 3295.04,6465.04 3300,6470 3300,6480 ; U7.9@3271.73,6484.73 3295.27,6484.73 3300,6480 ; U7.10@3271.73,6504.41 3295.59,6504.41 ; U7.11@3271.73,6524.1 3300,6524.1 ; v1@3318,6518 v1(3325,6518) 3318.9,6524.1 3300,6524.1 ; R56.1@3358.43,6324.57 R56.1@3360,6326.14 ; 3295.59,6504.41 3300,6508.82 3300,6524.1 ; 3295.59,6504.41 3300,6500 3300,6480
  Top Layer w20: 2109,6755.13 2109,6768 2111,6770 v1(2111,6777)
  Top Layer w30: v1(2111,6777) 2111,6806.81 2111.5,6807.31 C273.1@2111.5,6827 ; L1.1@2856.93,6067.48 2869.84,6054.57 C47.1@3156.93,6054.57 C56.1@3286.93,6054.57 ; v1(3417,6308) 3400.43,6324.57 R56.1@3358.43,6324.57 3358.43,6078.43 3334.57,6054.57 C56.1@3286.93,6054.57 ; C74.1@3930,5610.2 C73.1@3850,5610.2 3850,5660 3794.65,5715.35 U9.1@3750.16,5715.35 3750.16,5799.84 3730,5820 3410,5820 3280,5950 3280,6047.64 C56.1@3286.93,6054.57 ; v1(4159,6536) 4161.32,6533.68 C39.1@4161.32,6419.84 4285.73,6419.84 C40.1@4301.32,6404.25 4332.75,6404.25 4389,6348 4389,6374 4418,6403 4465,6403 4489,6379 4489,6343.46 4491.83,6340.63 U6.3@4492.3,6340.63
  Top Layer w40: U7.6@3242,6412 3329,6412 3360,6381 R56.1@3360,6326.14
  Bottom Layer w30: v1(3325,6518) 3325,6400 v1(3417,6308)
+12V: D1.2 D2.2 D3.2 D4.2 D5.2 D6.2 D8.2 D9.2 D11.1 D18.2 D19.2 D20.2 D21.2 D22.2 D23.2 D25.2 D26.2 D27.2 D28.2 D29.2 D30.2 D31.2 D32.2 D34.2 D35.2 D36.2 D37.2 D38.2 D39.2 D40.2 D41.2 D43.2 D44.2 D45.2 D46.2 D47.2 D48.2 D49.2 D50.2 D52.2 D53.2 D54.2 D55.2 D56.2 D57.2 D58.2 D59.2 D61.2 D62.2 J1.19 J5.39 J6.19 J7.19 J8.19 J9.19 J10.19 R58.2 R69.1 R310.1 R314.1 R315.1 R319.1 R320.1 R324.1 R325.1 R329.1 R330.1 R334.1 R335.1 TP7.1 | length 3765.9
  Top Layer w10: D49.2@1033.84,1332.55 1085.65,1332.55 v1(1088.25,1329.96) ; D47.2@1033.84,1472.55 1075.65,1472.55 v1(1078.25,1469.96) ; D45.2@1033.85,1592.55 1085.66,1592.55 v1(1088.26,1589.95) ; D52.2@1033.85,1732.55 1075.66,1732.55 v1(1078.26,1729.95) ; D50.2@1033.84,1872.55 1075.65,1872.55 v1(1078.25,1869.96) ; D4.2@1035.59,4812.6 1087.4,4812.6 v1(1090,4810) ; D30.2@1037.95,2922.6 1087.4,2922.6 v1(1090,2920) ; D35.2@1037.95,3182.6 1097.4,3182.6 v1(1100,3180) ; D31.2@1037.95,3302.6 1097.4,3302.6 v1(1100,3300) ; D29.2@1037.95,3432.6 1087.4,3432.6 v1(1090,3430) ; D27.2@1037.95,3552.6 1097.4,3552.6 v1(1100,3550) ; D34.2@1037.95,3682.6 1087.4,3682.6 v1(1090,3680) ; D32.2@1037.95,3812.6 1097.4,3812.6 v1(1100,3810) ; D53.2@1043.84,1202.55 1095.65,1202.55 v1(1098.25,1199.96) ; D48.2@1053.84,942.55 1105.65,942.55 v1(1108.25,939.96) ; D28.2@1057.95,3052.6 1117.4,3052.6 v1(1120,3050) ; D46.2@1063.84,1072.55 1115.65,1072.55 v1(1118.25,1069.96) ; D9.2@1065.59,5082.6 1117.4,5082.6 v1(1120,5080) ; D5.2@1065.59,5202.6 1117.4,5202.6 v1(1120,5200) ; D3.2@1065.59,5332.6 1127.4,5332.6 v1(1130,5330) ; D1.2@1065.59,5452.6 1127.4,5452.6 v1(1130,5450) ; D8.2@1065.59,5592.6 1117.4,5592.6 v1(1120,5590) ; D6.2@1065.59,5722.6 1127.4,5722.6 v1(1130,5720) ; D2.2@1075.59,4942.6 1127.4,4942.6 v1(1130,4940) ; v1(1234,3116) 1239.38,3116 R320.1@1280.38,3075 ; v1(1244,3985) 1246.38,3985 R319.1@1286.38,3945 ; v3@1694,5811 v3(1694,5810) 1717.62,5786.38 R69.1@1717.62,5774 ; R310.1@1727.62,4970 1780,4970 v1(1782,4968) ; R314.1@5823.62,1098 5823.62,1060.38 5834.96,1049.04 v1(5867,1049.04) ; R315.1@5864.62,1936 5867,1936 v1(5912,1891) ; D38.2@6167.64,3352.6 6227.09,3352.6 v1(6229.69,3350) ; D40.2@6167.64,3492.6 6222.28,3492.6 v1(6229.69,3500) ; D44.2@6167.64,3632.6 6227.09,3632.6 v1(6229.69,3630) ; D37.2@6167.64,3762.6 6227.09,3762.6 v1(6229.69,3760) ; D39.2@6167.64,3892.6 6212.28,3892.6 v1(6219.69,3900) ; D41.2@6177.64,2952.6 6217.09,2952.6 v1(6219.69,2950) ; D43.2@6177.64,3082.6 6237.09,3082.6 v1(6239.69,3080) ; D36.2@6177.64,3222.6 6227.09,3222.6 v1(6229.69,3220) ; D61.2@6177.64,4941.57 6238.43,4941.57 v1(6240,4940) ; D54.2@6177.64,5091.57 6238.43,5091.57 v1(6240,5090) ; D56.2@6177.64,5221.57 6238.43,5221.57 v1(6240,5220) ; D58.2@6177.64,5361.57 6238.43,5361.57 v1(6240,5360) ; D62.2@6177.64,5501.57 6238.43,5501.57 v1(6240,5500) ; D55.2@6177.64,5641.57 6228.43,5641.57 v1(6230,5640) ; D57.2@6177.64,5791.57 6238.43,5791.57 v1(6240,5790) ; D59.2@6187.64,4801.57 6238.43,4801.57 v1(6240,4800) ; D26.2@6197.64,1742.6 6252.28,1742.6 v1(6259.69,1750) ; D19.2@6197.64,1872.6 6257.09,1872.6 v1(6259.69,1870) ; D23.2@6207.64,1062.6 6257.09,1062.6 v1(6259.69,1060) ; D25.2@6207.64,1202.6 6257.09,1202.6 v1(6259.69,1200) ; D18.2@6207.64,1332.6 6257.09,1332.6 v1(6259.69,1330) ; D20.2@6207.64,1472.6 6257.09,1472.6 v1(6259.69,1470) ; D22.2@6207.64,1612.6 6252.28,1612.6 v1(6259.69,1620) ; D21.2@6207.64,2002.6 6247.09,2002.6 v1(6249.69,2000)
  Top Layer w15: v1(1359,1034) 1395,998 R330.1@1405.38,998 ; v1(1359,1958) 1360,1957 R329.1@1417.38,1957 ; R334.1@5868.62,4890 5891,4890 v1(5922,4859) ; R325.1@5877.62,3810 5901,3810 v1(5934,3777) ; R335.1@5887.62,5768 5892,5768 5936,5724 v1(5936,5722)
  Top Layer w30: R58.2@5290,6691.5 5403.9,6691.5 TP7.1@5405.39,6690 5533.53,6690 D11.1@5535.53,6688 ; R324.1@5866.62,2957 5874,2957 5912,2919 v1(5912,2917)
+14V: J2.1 J11.1 R59.1 R65.1 | length 2288.3
  Top Layer w20: R65.1@4818.5,6500 R59.1@4818.5,6580
  Top Layer w30: J2.1@2780,6850 2850,6850 2880,6880 3890,6880 4198,6572 J11.1@4289,6572 4518,6572 4590,6500 R65.1@4818.5,6500
-12V: D1.1 D2.1 D3.1 D4.1 D5.1 D6.1 D8.1 D9.1 D14.2 D18.1 D19.1 D20.1 D21.1 D22.1 D23.1 D25.1 D26.1 D27.1 D28.1 D29.1 D30.1 D31.1 D32.1 D34.1 D35.1 D36.1 D37.1 D38.1 D39.1 D40.1 D41.1 D43.1 D44.1 D45.1 D46.1 D47.1 D48.1 D49.1 D50.1 D52.1 D53.1 D54.1 D55.1 D56.1 D57.1 D58.1 D59.1 D61.1 D62.1 J1.20 J5.40 J6.20 J7.20 J8.20 J9.20 J10.20 R67.2 R311.1 R312.1 R316.1 R317.1 R321.1 R322.1 R326.1 R327.1 R331.1 R332.1 R336.1 R337.1 TP8.1 | length 4450.2
  Top Layer w10: v1(918.26,1589.95) 920.85,1592.55 D45.1@982.67,1592.55 ; v1@920,3440 v1@927.4,3432.6 ; v1(920,3550) 922.6,3552.6 D27.1@986.77,3552.6 ; v1(928.25,1199.96) 930.85,1202.55 D53.1@992.66,1202.55 ; v1(928.25,1329.96) 930.85,1332.55 D49.1@982.66,1332.55 ; v1(928.25,1479.96) 928.25,1469.96 930.85,1472.55 D47.1@982.66,1472.55 ; v1(928.26,1729.95) 930.85,1732.55 D52.1@982.67,1732.55 ; v1(928.25,1869.96) 930.85,1872.55 D50.1@982.66,1872.55 ; v1(930,2920) 932.6,2922.6 D30.1@986.77,2922.6 ; v1(930,3180) 932.6,3182.6 D35.1@986.77,3182.6 ; v1(930,3300) 932.6,3302.6 D31.1@986.77,3302.6 ; v1(930,3430) v1@927.4,3432.6 ; v1(930,3680) 932.6,3682.6 D34.1@986.77,3682.6 ; v1(930,3810) 932.6,3812.6 D32.1@986.77,3812.6 ; v1(930,4810) 932.6,4812.6 D4.1@984.41,4812.6 ; v1(938.25,939.96) 948.25,939.96 950.85,942.55 D48.1@1002.66,942.55 ; v1@940,5340 v1@947.4,5332.6 ; v1(940,5450) 942.6,5452.6 D1.1@1014.41,5452.6 ; v1(950,3050) 952.6,3052.6 D28.1@1006.77,3052.6 ; v1(950,5080) 952.6,5082.6 D9.1@1014.41,5082.6 ; v1(950,5200) 952.6,5202.6 D5.1@1014.41,5202.6 ; v1(950,5330) v1@947.4,5332.6 ; v1(950,5590) 952.6,5592.6 D8.1@1014.41,5592.6 ; v1(950,5720) 952.6,5722.6 D6.1@1014.41,5722.6 ; v1(958.25,1069.96) 960.85,1072.55 D46.1@1012.66,1072.55 ; v1(970,4940) 972.6,4942.6 D2.1@1024.41,4942.6 ; D29.1@986.77,3432.6 v1@927.4,3432.6 ; D3.1@1014.41,5332.6 v1@947.4,5332.6 ; v1(1237,2980) 1238,2981 1238,2983 1241.38,2983 R322.1@1280.38,3022 ; v1(1245,3848) 1246.38,3848 R321.1@1287.38,3889 ; v1(1285,4919) 1284,4918 1284,4902.38 R312.1@1314.38,4872 ; R311.1@1725.62,5676 1726.62,5677 v1(1781,5677) ; R316.1@5799.62,1178 5859,1178 5863,1182 v1(5863,1181) ; R317.1@5864.62,1989 5869,1989 5912,2032 v1(5912,2033) ; v1(6039.69,3490) 6042.28,3492.6 D40.1@6116.46,3492.6 ; v1(6039.69,3630) 6042.28,3632.6 D44.1@6116.46,3632.6 ; v1(6039.69,3890) 6042.28,3892.6 D39.1@6116.46,3892.6 ; v1(6040,4940) 6041.57,4941.57 D61.1@6126.46,4941.57 ; v1(6040,5090) 6041.57,5091.57 D54.1@6126.46,5091.57 ; v1(6040,5220) 6041.57,5221.57 D56.1@6126.46,5221.57 ; v1(6049.69,3090) 6057.09,3082.6 D43.1@6126.46,3082.6 ; v1(6049.69,3220) 6052.28,3222.6 D36.1@6126.46,3222.6 ; v1(6049.69,3350) 6052.28,3352.6 D38.1@6116.46,3352.6 ; v1(6049.69,3760) 6052.28,3762.6 D37.1@6116.46,3762.6 ; v1(6050,5360) 6051.57,5361.57 D58.1@6126.46,5361.57 ; v1(6050,5500) 6051.57,5501.57 D62.1@6126.46,5501.57 ; v1@6050,5650 v1@6058.43,5641.57 ; v1(6050,5790) 6051.57,5791.57 D57.1@6126.46,5791.57 ; v1(6059.69,2950) 6062.28,2952.6 D41.1@6126.46,2952.6 ; v1(6060,4800) 6061.57,4801.57 D59.1@6136.46,4801.57 ; v1(6060,5640) v1@6058.43,5641.57 ; v1(6079.69,1330) 6082.28,1332.6 D18.1@6156.46,1332.6 ; v1(6079.69,1480) 6087.09,1472.6 D20.1@6156.46,1472.6 ; v1(6079.69,1610) 6082.28,1612.6 D22.1@6156.46,1612.6 ; v1(6079.69,1740) 6082.28,1742.6 D26.1@6146.46,1742.6 ; v1(6079.69,1870) 6082.28,1872.6 D19.1@6146.46,1872.6 ; v1(6089.69,1060) 6092.28,1062.6 D23.1@6156.46,1062.6 ; v1(6089.69,1200) 6092.28,1202.6 D25.1@6156.46,1202.6 ; v1(6089.69,2000) 6092.28,2002.6 D21.1@6156.46,2002.6 ; D55.1@6126.46,5641.57 v1@6058.43,5641.57
  Top Layer w15: v1(1356,1834) 1359,1837 R331.1@1418.38,1837 ; v1(1358,878) 1404.38,924.38 R332.1@1404.38,925 ; R336.1@5868.62,4947 5897,4947 v1(5931,4981) ; R327.1@5878.62,3870 5917.62,3909 v1(5930,3909) ; R337.1@5887.62,5827 5891,5827 5931,5867 v1(5937,5867)
  Top Layer w30: TP8.1@5320,6230 5426.89,6230 R67.2@5455.39,6258.5 5460.04,6258.5 5480.47,6278.94 5483.57,6278.94 5594.53,6389.9 D14.2@5594.53,6393 ; R326.1@5864.62,3018 5879,3018 5913,3052 v1(5913,3053)
  Bottom Layer w10: v1(5912,2033) 5912,2024 v1@5913,2023
-14V: J4.1 J12.1 R61.1 | length 1706.5
  Top Layer w30: J12.1@4701,6247 4803,6247 v1(4820,6230) 4820,6301.5 R61.1@4828.5,6310
  Bottom Layer w30: J4.1@3460,6110 3530,6040 4680,6040 4820,6180 v1(4820,6230)
A0+: D1.3 J1.11 R1.1 | length 658.5
  Top Layer w10: J1.11@760,5480 900,5480 950,5530 1037.4,5530 D1.3@1040,5527.4 1192.6,5527.4 1260,5460 1260,5410 1281.18,5388.82 R1.1@1310,5388.82
A0-: J1.12 R12.2 R14.1 | length 2834.7
  Top Layer w15: v1(1600,6180) v1(1790,6180) ; v1(2010,5790) 2045.76,5754.24 R14.1@2045.76,5733.62
  Top Layer w20: R12.2@431.5,5480 J1.12@660,5480
  Bottom Layer w15: J1.12@660,5480 530,5480 510,5500 510,6070 620,6180 v1(1600,6180) ; v1(1790,6180) 2010,5960 v1(2010,5790)
A1+: D3.3 J1.9 R18.1 | length 1039.5
  Top Layer w10: J1.9@760,5380 863.23,5380 890.63,5407.4 D3.3@1040,5407.4 1172.6,5407.4 1230,5350 1681.18,5350 R18.1@1740,5408.82
A1-: J1.10 R11.2 R17.1 | length 2999.9
  Top Layer w15: v1(1840,5710) 1840,5711 1863,5734 1895.4,5734 R17.1@1895.78,5733.62
  Top Layer w20: R11.2@431.5,5380 J1.10@660,5380
  Bottom Layer w15: J1.10@660,5380 510,5380 470,5420 470,6080 610,6220 1670,6220 1840,6050 v1(1840,5710)
A2+: D5.3 J1.7 R35.1 | length 1029.3
  Top Layer w10: J1.7@760,5280 1037.4,5280 D5.3@1040,5277.4 1187.4,5277.4 1210,5300 1687.18,5300 R35.1@1752,5235.18
A2-: J1.8 R10.2 R24.1 | length 2888.1
  Top Layer w15: v1(1830,4900) 1857.66,4872.34 R24.1@1883.5,4872.34
  Top Layer w20: R10.2@431.5,5280 J1.8@660,5280
  Bottom Layer w15: J1.8@660,5280 520,5280 480,5240 480,4740 772.87,4447.13 1757.13,4447.13 1850,4540 1850,4620 1830,4640 v1(1830,4900)
A3+: D9.3 J1.5 R44.1 | length 608
  Top Layer w10: J1.5@760,5180 840,5180 870,5150 1032.6,5150 D9.3@1040,5157.4 1167.4,5157.4 1260,5250 1306.82,5250 R44.1@1312,5255.18
A3-: J1.6 R9.2 R26.1 | length 2743.6
  Top Layer w15: v1(1710,4480) 1720,4470 1870,4470 v1(1880,4480) ; v1(2000,4820) 2043.52,4863.52 R26.1@2043.52,4872.34
  Top Layer w20: R9.2@431.5,5180 J1.6@660,5180
  Bottom Layer w15: J1.6@660,5180 545.75,5180 515.75,5150 510,5150 510,4760 800,4470 1700,4470 v1(1710,4480) ; v1(1880,4480) 2000,4600 v1(2000,4820)
A4+: D2.3 J1.3 R3.1 | length 991.1
  Top Layer w10: J1.3@760,5080 840,5080 910,5010 1042.6,5010 D2.3@1050,5017.4 1212.6,5017.4 1250,4980 1250,4600 1277.81,4572.19 R3.1@1312,4572.19
A4-: J1.4 R8.2 R28.1 | length 2690.5
  Top Layer w15: v1(1760,4510) 1864.22,4510 1866.59,4512.37 1893.41,4512.37 1895.78,4510 v1(2050,4510) ; v1(2160,4820) 2201.73,4861.73 R28.1@2201.73,4876.38
  Top Layer w20: R8.2@431.5,5080 J1.4@660,5080
  Bottom Layer w15: J1.4@660,5080 566.77,5080 536.77,5050 536.77,4783.23 810,4510 1694.22,4510 1696.59,4512.37 1723.41,4512.37 1725.78,4510 v1(1760,4510) ; v1(2050,4510) 2160,4620 v1(2160,4820)
A5+: D4.3 J1.1 R20.1 | length 1352.3
  Top Layer w10: J1.1@760,4980 852.6,4887.4 D4.3@1010,4887.4 1172.6,4887.4 1220,4840 1220,4580 1270,4530 1699.81,4530 R20.1@1752,4582.19
A5-: J1.2 R7.2 R30.1 | length 2461.9
  Top Layer w20: R7.2@431.5,4980 J1.2@660,4980 ; v1(1810,4580) v1(2260,4580) ; v1(2320,4810) 2348.26,4838.26 R30.1@2348.26,4869.95
  Bottom Layer w20: J1.2@660,4980 660,4760 840,4580 1430.68,4580 1445.55,4594.87 1474.45,4594.87 1489.32,4580 v1(1810,4580) ; v1(2260,4580) 2320,4640 v1(2320,4810)
A6+: D6.3 J1.15 R37.1 | length 1254.9
  Top Layer w10: J1.15@760,5680 840,5680 957.4,5797.4 D6.3@1040,5797.4 1057.4,5797.4 1170,5910 1170,6010 1260,6100 1671.81,6100 R37.1@1750,6021.81
A6-: J1.16 R6.2 R32.1 | length 2611.2
  Top Layer w15: v1(1720,6110) 1874.22,6110 1876.59,6107.63 1886.59,6107.63 1913.41,6107.63 1915.78,6110 v1(1970,6110) ; v1(2320,5790) 2350,5760 R32.1@2350,5733.06
  Top Layer w20: R6.2@431.5,5680 J1.16@660,5680
  Bottom Layer w15: J1.16@660,5680 602.05,5680 582.05,5700 582.05,6012.05 680,6110 1494.22,6110 1496.59,6107.63 1523.41,6107.63 1525.78,6110 v1(1720,6110) ; v1(1970,6110) 2290,5790 v1(2320,5790)
A7+: D8.3 J1.13 R40.1 | length 867.1
  Top Layer w10: J1.13@760,5580 870,5580 957.4,5667.4 D8.3@1040,5667.4 1157.4,5667.4 1240,5750 1240,5981.81 R40.1@1300,6041.81
A7-: J1.14 R5.2 R34.1 | length 2731.9
  Top Layer w15: v1(1510,6140) 1704.22,6140 1706.59,6142.37 1733.41,6142.37 1735.78,6140 v1(1890,6140) ; v1(2160,5790) 2200,5750 R34.1@2200,5730.78
  Top Layer w20: R5.2@431.5,5580 J1.14@660,5580
  Bottom Layer w15: J1.14@660,5580 570,5580 540,5610 540,6040 640,6140 1500,6140 v1@1510,6150 ; v1(1890,6140) 1900,6140 1937.63,6102.37 1937.63,6096.59 2160,5874.22 v1(2160,5790)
